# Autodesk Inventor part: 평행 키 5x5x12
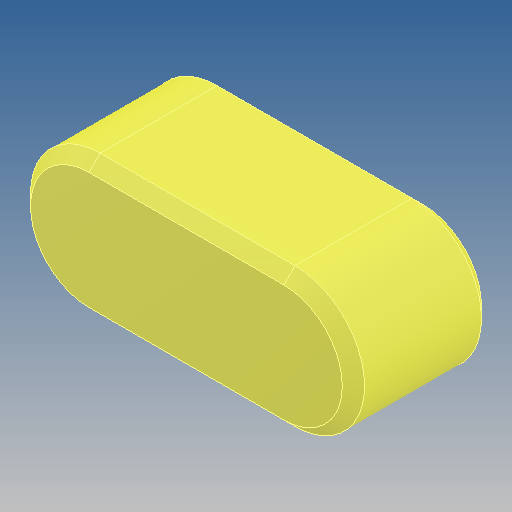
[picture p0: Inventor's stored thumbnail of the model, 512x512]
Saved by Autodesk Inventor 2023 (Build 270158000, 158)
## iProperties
Created: 2025-03
Part Number: 평행 키 5x5x12
Material: 강철, 연강
Description: 키 및 해당 키홈
Document SubType Name: Modeling
Designer: Admin
Density: 7.85 g/cm^3
Appearance: 기본값
Author: jhkim
Sending System: Autodesk Inventor 2025
Preprocessor: ST-DEVELOPER v20
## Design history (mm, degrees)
node "평행 키 5x5x121"
node "솔리드1"
body "Solid1"
